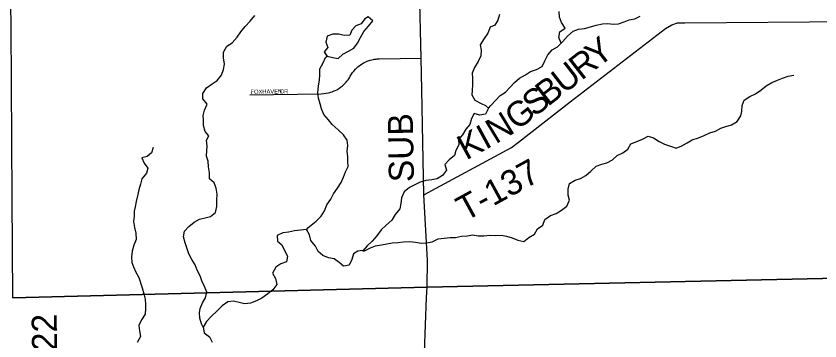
# Model space of a CAD drawing. Extents: x 1985906 to 2277390, y 930619 to 1324581.
# Drawn here: x 2139705 to 2149336, y 1165979 to 1169867 of the extents above; entities that cross this region are included whole.
import ezdxf

# ---------------------------------------------------------------- set-up
doc = ezdxf.new("R2010")
doc.units = 0
for name, color, linetype in [('GM_X_County_Road_Text', 7, 'Continuous'), ('GM_X_Minor_Lake', 7, 'Continuous'), ('GM_X_Minor_River', 7, 'Continuous'), ('GM_X_Township', 7, 'Continuous'), ('GM_X_Township_Road', 7, 'Continuous'), ('GM_X_Township_Road_Text', 7, 'Continuous'), ('GM_X_Township_Subdivision', 7, 'Continuous'), ('GM_X_Township_Subdivision_Text', 7, 'Continuous')]:
    doc.layers.add(name, color=color, linetype=linetype)

msp = doc.modelspace()

# ---------------------------------------------------------------- linework, layer by layer
at = {"layer": 'GM_X_Minor_Lake'}
for points in [[(2143925.4, 1169859.1), (2143885.4, 1169835), (2143841.5, 1169772.9), (2143777.6, 1169752.8), (2143727.7, 1169698.7), (2143703.7, 1169638.6), (2143635.8, 1169636.5), (2143571.9, 1169650.5), (2143500, 1169652.5), (2143434.1, 1169626.4), (2143416.1, 1169556.3), (2143442.1, 1169492.2), (2143396.2, 1169438.1), (2143430.3, 1169388.5)], [(2143925.4, 1169859.1), (2143885.4, 1169835), (2143841.5, 1169772.9), (2143777.6, 1169752.8), (2143727.7, 1169698.7), (2143703.7, 1169638.6), (2143635.8, 1169636.5), (2143571.9, 1169650.5), (2143500, 1169652.5), (2143434.1, 1169626.4), (2143416.1, 1169556.3), (2143442.1, 1169492.2), (2143396.2, 1169438.1), (2143436.2, 1169380)], [(2143414.1, 1169373.6), (2143432.2, 1169388), (2143500.1, 1169370), (2143566, 1169360), (2143621.9, 1169410.1), (2143687.8, 1169446.2), (2143751.7, 1169482.3), (2143797.6, 1169544.4), (2143831.6, 1169612.6), (2143871.5, 1169682.7), (2143929.4, 1169746.9), (2143979.3, 1169809), (2143925.4, 1169859.1)], [(2143430.3, 1169388.5), (2143500.1, 1169370), (2143566, 1169360), (2143621.9, 1169410.1), (2143687.8, 1169446.2), (2143751.7, 1169482.3), (2143797.6, 1169544.4), (2143831.6, 1169612.6), (2143871.5, 1169682.7), (2143929.4, 1169746.9), (2143979.3, 1169809), (2143925.4, 1169859.1)]]:
    msp.add_lwpolyline(points, dxfattribs=at)
at = {"layer": 'GM_X_Minor_River'}
for points in [[(2141946.8, 1166141.9), (2141925.9, 1166183.5), (2141908.4, 1166251.2), (2141904.9, 1166315.3), (2141909.7, 1166365.5), (2141938.1, 1166434.2), (2141974.7, 1166495.2), (2141991, 1166563.7), (2141963.5, 1166631.2), (2141930.1, 1166696.5), (2141910.7, 1166758.2), (2141873.1, 1166827.4), (2141849.7, 1166891), (2141812.3, 1166954.2), (2141774.8, 1167021.5), (2141755.4, 1167083.2), (2141731.8, 1167154.7), (2141710.2, 1167226.4), (2141722.6, 1167292.8), (2141777.2, 1167350.1), (2141840, 1167401.7), (2141903.1, 1167435.2), (2141970.6, 1167450.8), (2142036.1, 1167468.3), (2142092.9, 1167517.7), (2142109.2, 1167590.2), (2142111.5, 1167662.4), (2142113.8, 1167736.6), (2142104.2, 1167808.5), (2142078.7, 1167872), (2142021.8, 1167918.8), (2142024.1, 1167991), (2142012.4, 1168062.8), (2142004.9, 1168130.8), (2141985.5, 1168192.5), (2141990, 1168258.7), (2141996.8, 1168310.9), (2141985.1, 1168382.8), (2142013.9, 1168435.6), (2141972.7, 1168486.7), (2141949.2, 1168556.3), (2141949.6, 1168624.4), (2141948.4, 1168678.5), (2141962.9, 1168740.9), (2141993.2, 1168811.8), (2141941.8, 1168876.7), (2141944.3, 1168940.9), (2141986.7, 1169008), (2142055.5, 1169057.7), (2142114.5, 1169097.1), (2142165, 1169158.4), (2142189.4, 1169227.1), (2142201.9, 1169291.5), (2142190.1, 1169367.3), (2142192.5, 1169435.5), (2142228.8, 1169508.5), (2142293.9, 1169546.1), (2142356.1, 1169615.6), (2142396.6, 1169678.7), (2142449.1, 1169744), (2142509.5, 1169805.5), (2142565.9, 1169872.9)], [(2145497.1, 1169886.7), (2145476.7, 1169820.1), (2145442.2, 1169757.1), (2145384.8, 1169735.8), (2145356.5, 1169665), (2145312, 1169599.9), (2145265.8, 1169524.6), (2145279.3, 1169458.8), (2145272.9, 1169390.6), (2145242.4, 1169325.8), (2145196.2, 1169252.6), (2145171.8, 1169183.9), (2145173.3, 1169119.8), (2145172.9, 1169049.6), (2145170.6, 1168975.5), (2145167.8, 1168925.3), (2145203.2, 1168860), (2145276, 1168819.6), (2145328.4, 1168798.8)], [(2145364.6, 1168766.7), (2145392.4, 1168798.2), (2145505.5, 1168917.1), (2145568.4, 1168958.6), (2145623.1, 1169012), (2145675.6, 1169071.3), (2145738.4, 1169122.8), (2145807.3, 1169164.5), (2145870.3, 1169206), (2145941.6, 1169229.7), (2146008.7, 1169265.3), (2146039.1, 1169332.2), (2146077.4, 1169405.2), (2146129.9, 1169462.5), (2146193, 1169500), (2146253.5, 1169559.5), (2146311.8, 1169629), (2146378.4, 1169688.6), (2146445.7, 1169712.2), (2146517.4, 1169719.9), (2146588.9, 1169737.6), (2146656.4, 1169757.2), (2146729.9, 1169772.9), (2146793.7, 1169778.4), (2146857.7, 1169771.9), (2146923.5, 1169775.4), (2146992.9, 1169797.1), (2147052.2, 1169824.5), (2147119.8, 1169836.1), (2147181, 1169867.5)], [(2146235.7, 1169542), (2146208.4, 1169610.6), (2146220.8, 1169681), (2146283.7, 1169722.5), (2146240.2, 1169789.6), (2146216.8, 1169855.2), (2146211.2, 1169923.2)], [(2143187.2, 1167314.1), (2143199.5, 1167331.4), (2143240.7, 1167364), (2143301.5, 1167411.4), (2143360, 1167472.9), (2143402.5, 1167536), (2143426.8, 1167608.7), (2143475.1, 1167677.9), (2143509.6, 1167740.8), (2143556, 1167806), (2143602.3, 1167875.2), (2143628.9, 1167938), (2143653.3, 1168004.6), (2143683.8, 1168067.5), (2143678.4, 1168129.4), (2143679.2, 1168181.6), (2143671.6, 1168249.5), (2143680, 1168319.8), (2143670.5, 1168383.7), (2143627.1, 1168446.8), (2143563.8, 1168507.5), (2143494.5, 1168570), (2143447.3, 1168625), (2143393.9, 1168687.9), (2143366.4, 1168755.4), (2143349, 1168819.1), (2143329.5, 1168884.8), (2143322, 1168948.7), (2143328.1, 1169031), (2143342.5, 1169099.4), (2143345, 1169165.6), (2143343.4, 1169237.7), (2143383.7, 1169306.8), (2143414.1, 1169373.6)], [(2143858.9, 1167055.7), (2143880.8, 1167058.2), (2143949.8, 1167093.9), (2144011.2, 1167119.3), (2144082.8, 1167131), (2144146.4, 1167142.5), (2144210.1, 1167152), (2144277.9, 1167157.6), (2144347.6, 1167165.2), (2144419.4, 1167168.8), (2144491.5, 1167160.5), (2144557.7, 1167148), (2144621.5, 1167151.5), (2144691, 1167167.1), (2144762.1, 1167200.8), (2144833.8, 1167210.5), (2144905.5, 1167218.2), (2144971.4, 1167217.7), (2145041, 1167231.3), (2145110.7, 1167238.9), (2145178.4, 1167248.5), (2145242.5, 1167238), (2145310.5, 1167237.6), (2145382.2, 1167245.2), (2145448.2, 1167240.7), (2145520, 1167244.4), (2145582.2, 1167231.8), (2145648.5, 1167211.3), (2145717, 1167186.9), (2145787.3, 1167170.4), (2145850.1, 1167218), (2145915.1, 1167257.6), (2145951.5, 1167322.5), (2146014.5, 1167364.1), (2146038.9, 1167430.7), (2146109.6, 1167480.4), (2146175, 1167506), (2146242, 1167543.6), (2146304.7, 1167593.2), (2146337.1, 1167664), (2146321.7, 1167725.8), (2146320.1, 1167793.9), (2146334.5, 1167864.3), (2146403.5, 1167902), (2146466.9, 1167923.5), (2146529.9, 1167961), (2146592.6, 1168012.6), (2146655.2, 1168070.1), (2146722.6, 1168093.7), (2146784.1, 1168109.2), (2146851.2, 1168146.8), (2146907.9, 1168198.2), (2146973.1, 1168229.7), (2147036, 1168273.3), (2147072.4, 1168338.2), (2147141.7, 1168365.9), (2147208.9, 1168395.5), (2147280, 1168429.2), (2147342.3, 1168410.6), (2147411.2, 1168368.1), (2147475.9, 1168333.6), (2147544.4, 1168309.1), (2147612.8, 1168286.6), (2147682, 1168314.3), (2147745.1, 1168351.8), (2147804.2, 1168387.2), (2147881.6, 1168409.1), (2147950.8, 1168438.7), (2148018, 1168468.3), (2148083.3, 1168491.9), (2148148.4, 1168527.4), (2148209.9, 1168546.9), (2148277.3, 1168566.5), (2148344.3, 1168606.1), (2148386.7, 1168675.2), (2148399.5, 1168725.6), (2148405.9, 1168795.9), (2148428.3, 1168862.5), (2148497.2, 1168904.2), (2148564.4, 1168935.8), (2148627.3, 1168979.3), (2148692, 1169030.9), (2148761, 1169070.6), (2148828.2, 1169102.2), (2148889.5, 1169125.6), (2148954.9, 1169149.2), (2149024.5, 1169160.8)], [(2145328.4, 1168798.8), (2145367.2, 1168763.6), (2145328.9, 1168692.6), (2145263.3, 1168681.1), (2145194.9, 1168699.5), (2145160.3, 1168640.6), (2145140, 1168570), (2145095.4, 1168512.9), (2145053, 1168445.8), (2145004.3, 1168390.6), (2145011.8, 1168326.6), (2144973.5, 1168257.6), (2144958.9, 1168197.1), (2144896.1, 1168147.6), (2144843.5, 1168092.3), (2144863, 1168024.6), (2144812.6, 1167959.3), (2144751.6, 1167919.9), (2144686, 1167906.3), (2144616.2, 1167900.7), (2144548.8, 1167879.1), (2144483.7, 1167847.5), (2144420.5, 1167814), (2144355.8, 1167762.4), (2144321.5, 1167691.5), (2144315, 1167625.2), (2144302.6, 1167558.8), (2144248.2, 1167491.5), (2144207.8, 1167426.4), (2144141.3, 1167364.8), (2144078.7, 1167309.2), (2144026.4, 1167237.9), (2143971.9, 1167174.5), (2143913.3, 1167119.1), (2143858.9, 1167055.7)], [(2141348.1, 1168293.9), (2141329.6, 1168231.4), (2141276.7, 1168186.1), (2141213.2, 1168170.6), (2141240.6, 1168107.1), (2141283.9, 1168046), (2141267.4, 1167985.5), (2141211, 1167920.1), (2141194.5, 1167853.6), (2141176.1, 1167787), (2141161.7, 1167716.6), (2141145.3, 1167648.1), (2141130.8, 1167583.6), (2141122, 1167533.3), (2141119.4, 1167473.2), (2141112.9, 1167406.9), (2141124.6, 1167335), (2141142.1, 1167267.3), (2141143.8, 1167195.2), (2141115.4, 1167126.4), (2141095.1, 1167053.9), (2141088.7, 1166983.6), (2141094.2, 1166919.6), (2141111.4, 1166865.9), (2141138.8, 1166802.4), (2141174.3, 1166737.1), (2141217.1, 1166613.9), (2141234.6, 1166544.2), (2141252.1, 1166480.5), (2141257.6, 1166416.5), (2141256.7, 1166366.4), (2141252.3, 1166300.2), (2141207.9, 1166231), (2141177.6, 1166162.2), (2141183, 1166098.2), (2141196.6, 1166030.4), (2141158.2, 1165961.4)], [(2143858.9, 1167055.7), (2143856.7, 1167061.7), (2143801, 1167054.4), (2143747.8, 1167021.1), (2143727.4, 1166954.5), (2143695, 1166887.6), (2143627.4, 1166874), (2143576.4, 1166918.9), (2143517.5, 1166961.6), (2143447.4, 1166974.1), (2143378.9, 1167000.5), (2143323.8, 1167049.3), (2143292.4, 1167112.7), (2143238.9, 1167181.6), (2143219.4, 1167249.3), (2143184, 1167312.6), (2143112.2, 1167304.9), (2143040.6, 1167295.2), (2142969, 1167281.5), (2142903.3, 1167272), (2142834.2, 1167240.4), (2142835.7, 1167174.3), (2142890.6, 1167129.5), (2142920.2, 1167060), (2142955.7, 1166992.7), (2142945.3, 1166924.4), (2142877.9, 1166902.8), (2142816.9, 1166861.3), (2142776.6, 1166792.2), (2142812, 1166726.9), (2142827.7, 1166655.2), (2142783.2, 1166590), (2142720.4, 1166542.5), (2142651.7, 1166492.8), (2142584.6, 1166459.2), (2142513.3, 1166431.5), (2142443.6, 1166423.9), (2142379.3, 1166440.4), (2142311.1, 1166454.9), (2142243.3, 1166447.3), (2142176.6, 1166397.7), (2142112.1, 1166336.1), (2142045.6, 1166276.4), (2141985.2, 1166210.9), (2141946.8, 1166141.9), (2141958.3, 1166076.1), (2142021.4, 1166027.5), (2142054.8, 1165964.1)]]:
    msp.add_lwpolyline(points, dxfattribs=at)
at = {"layer": 'GM_X_Township'}
for points in [[(2165310.8, 1172112), (2165357.7, 1167072.5), (2163267.4, 1167027.3), (2159268.3, 1166940.7), (2154462.4, 1166836.7), (2149729, 1166734.2), (2144629.8, 1166623.8), (2139668.5, 1166493.7), (2139656.8, 1167688.3), (2139644.7, 1169748.4), (2139611.5, 1172078.9)], [(2139668.5, 1166493.7), (2144629.8, 1166623.8), (2149729, 1166734.2), (2154462.4, 1166836.7), (2159268.3, 1166940.7), (2163267.4, 1167027.3), (2165357.7, 1167072.5), (2165382.3, 1165399.2), (2165422.7, 1161230.6), (2165479.2, 1155198), (2165479, 1152728.9), (2165484.7, 1152262.1), (2165492.6, 1150411.1)]]:
    msp.add_lwpolyline(points, dxfattribs=at)
at = {"layer": 'GM_X_Township_Road'}
for points in [[(2144592.7, 1167727.3), (2144567.3, 1168983), (2144558.8, 1169364.2), (2144540.3, 1170198.7), (2144494.5, 1172175.5)], [(2144592.7, 1167727.3), (2145639.2, 1168296), (2145724.4, 1168356.9), (2146344.6, 1168841.5), (2147488.1, 1169717.7), (2147563.5, 1169764.5), (2147631.2, 1169785.2), (2147719, 1169786), (2149708.7, 1169802.9)], [(2144624.7, 1166498), (2144629.8, 1166623.8), (2144634.5, 1166947.8), (2144592.7, 1167727.3)], [(2144544.3, 1163628), (2144584.9, 1165515.8), (2144624.7, 1166498)]]:
    msp.add_lwpolyline(points, dxfattribs=at)
at = {"layer": 'GM_X_Township_Subdivision'}
msp.add_lwpolyline([(2142506.7, 1168923.6), (2143362, 1168938.3), (2143391.2, 1168939.7), (2143420.9, 1168943.3), (2143449.7, 1168948.9), (2143463, 1168952.3), (2143476.3, 1168956.2), (2143490.6, 1168960.9), (2143502, 1168965.1), (2143517.4, 1168971.4), (2143528.1, 1168976.3), (2143548.9, 1168986.7), (2143572, 1169000.3), (2143594.1, 1169015.4), (2143615.4, 1169032.1), (2143632.2, 1169047), (2143650.2, 1169065.1), (2143658.8, 1169074.6), (2143670, 1169087.9), (2143683.9, 1169106.3), (2143699, 1169129.1), (2143709.3, 1169146.9), (2143725.6, 1169174.2), (2143738, 1169192.1), (2143755.1, 1169213.7), (2143770.1, 1169230.5), (2143780.3, 1169240.9), (2143790.6, 1169250.7), (2143800.2, 1169259.2), (2143810.1, 1169267.3), (2143830.7, 1169282.9), (2143853.3, 1169297.6), (2143876, 1169310.4), (2143897, 1169320.6), (2143912.5, 1169327.1), (2143925.1, 1169331.9), (2143946.7, 1169339), (2143969.5, 1169345), (2143987.6, 1169348.8), (2143996.1, 1169350.3), (2144005.3, 1169351.7), (2144018, 1169353.3), (2144030.2, 1169354.4), (2144042.5, 1169355.1), (2144056.7, 1169355.5), (2144558.8, 1169364.2)], dxfattribs=at)

# ---------------------------------------------------------------- texts
at = {"layer": 'GM_X_County_Road_Text'}
msp.add_text('C-22', height=300, rotation=90.68709, dxfattribs=at).set_placement((2140202.1, 1165435.5))
at = {"layer": 'GM_X_Township_Road_Text'}
for s, rotation, p in [('Y', 37.91686, (2146673, 1169242.3)), ('R', 37.91127, (2146478.5, 1169090.9)), ('U', 37.91686, (2146270.3, 1168928.6)), ('B', 37.91249, (2146075.8, 1168777.2)), ('S', 37.91332, (2145916.2, 1168652.8)), ('G', 38.07949, (2145708.5, 1168490.2)), ('N', 31.30038, (2145451.1, 1168331)), ('SUB', 91.06035, (2144473.1, 1167882.2)), ('K', 28.61162, (2145097.9, 1168137.8)), ('I', 28.65816, (2145329.9, 1168264.3)), ('T-137', 28.69986, (2145087.7, 1167405.7))]:
    msp.add_text(s, height=300, rotation=rotation, dxfattribs=at).set_placement(p)
at = {"layer": 'GM_X_Township_Subdivision_Text'}
for s, rotation, p in [('FOXHAVEN', 0.75343, (2142514.3, 1168936.6)), ('DR', 0.00001, (2142866.5, 1168941))]:
    msp.add_text(s, height=50, rotation=rotation, dxfattribs=at).set_placement(p)

doc.saveas('drawing.dxf')
